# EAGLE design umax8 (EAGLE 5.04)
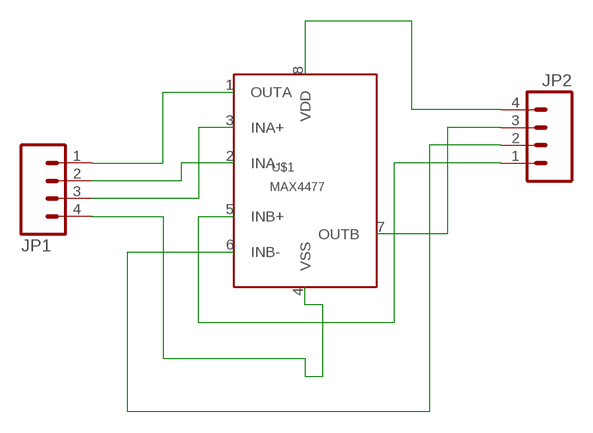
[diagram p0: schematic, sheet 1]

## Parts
JP1  M04PTH  [1X04]
JP2  M04PTH  [1X04]
U$1  MAX4477  [UMAX8]

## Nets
N$1: JP1.1 U$1.1(OUTA)
N$2: JP1.2 U$1.2(INA-)
N$3: JP1.3 U$1.3(INA+)
N$4: JP1.4 U$1.4(VSS)
N$5: JP2.1 U$1.5(INB+)
N$6: JP2.2 U$1.6(INB-)
N$7: JP2.3 U$1.7(OUTB)
N$8: JP2.4 U$1.8(VDD)

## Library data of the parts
JP1 JP2 = SparkFun:M04: Header 4 Standard 4-pin 0.1" header. Use with straight break away headers (SKU : PRT-00116), right angle break away headers (PRT-00553), swiss pins (PRT-00743), machine pins (PRT-00117), and female headers (PRT-00115). Molex polarized connector foot print use with SKU : PRT-08231 with associated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
U$1 = trl:MAX4477

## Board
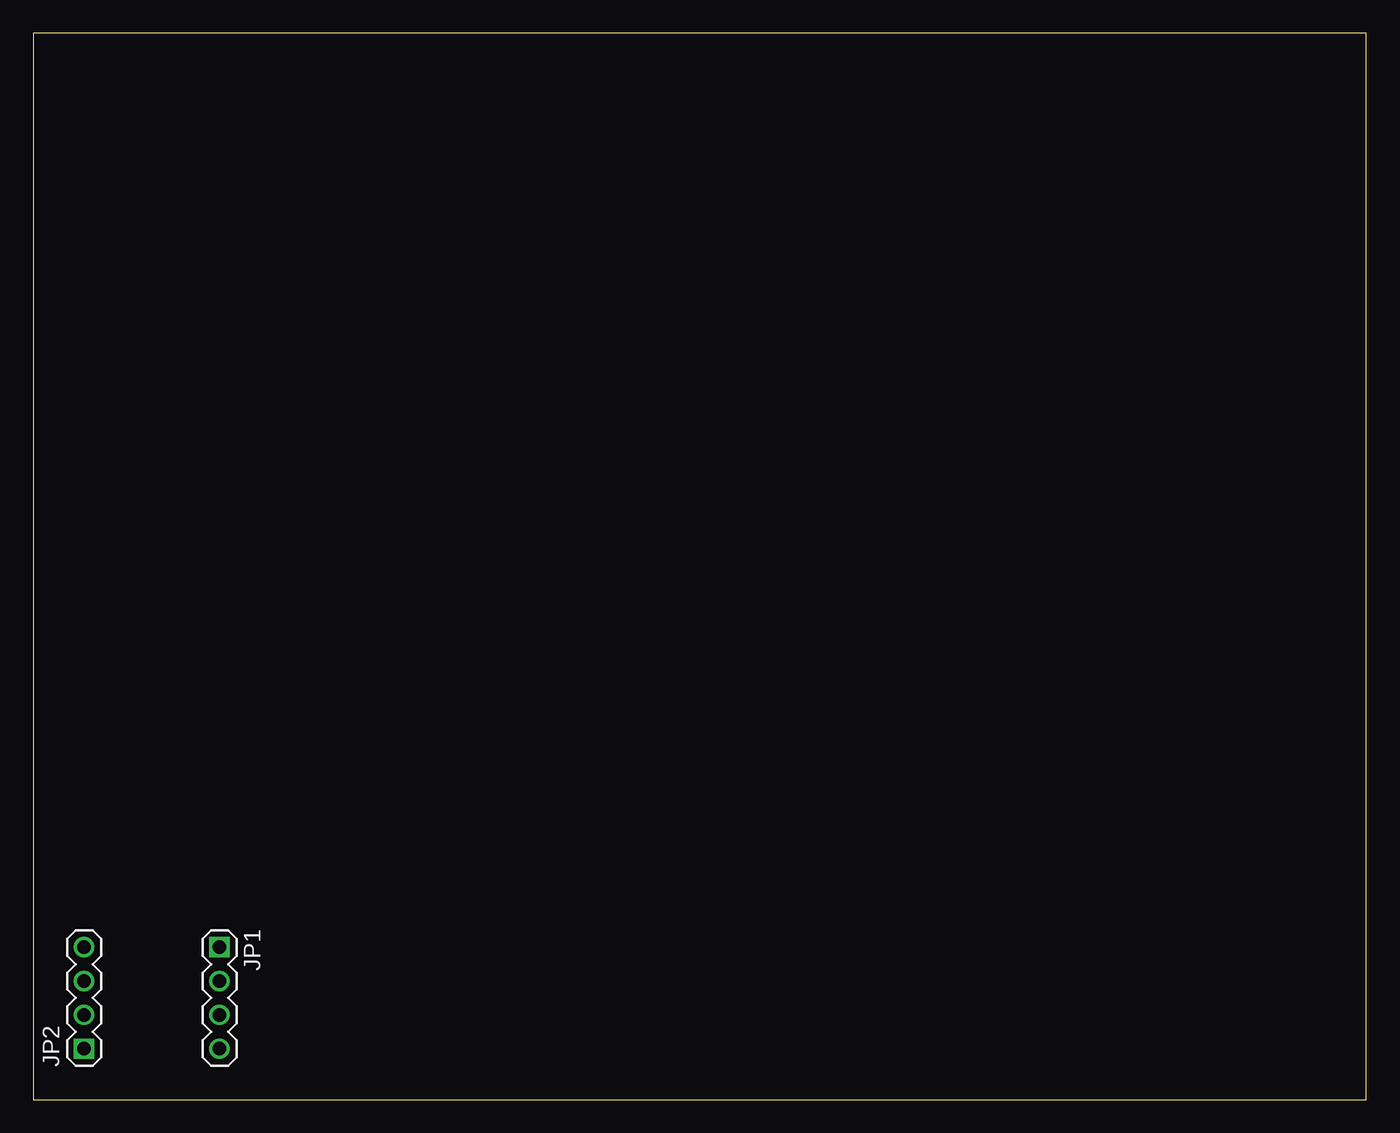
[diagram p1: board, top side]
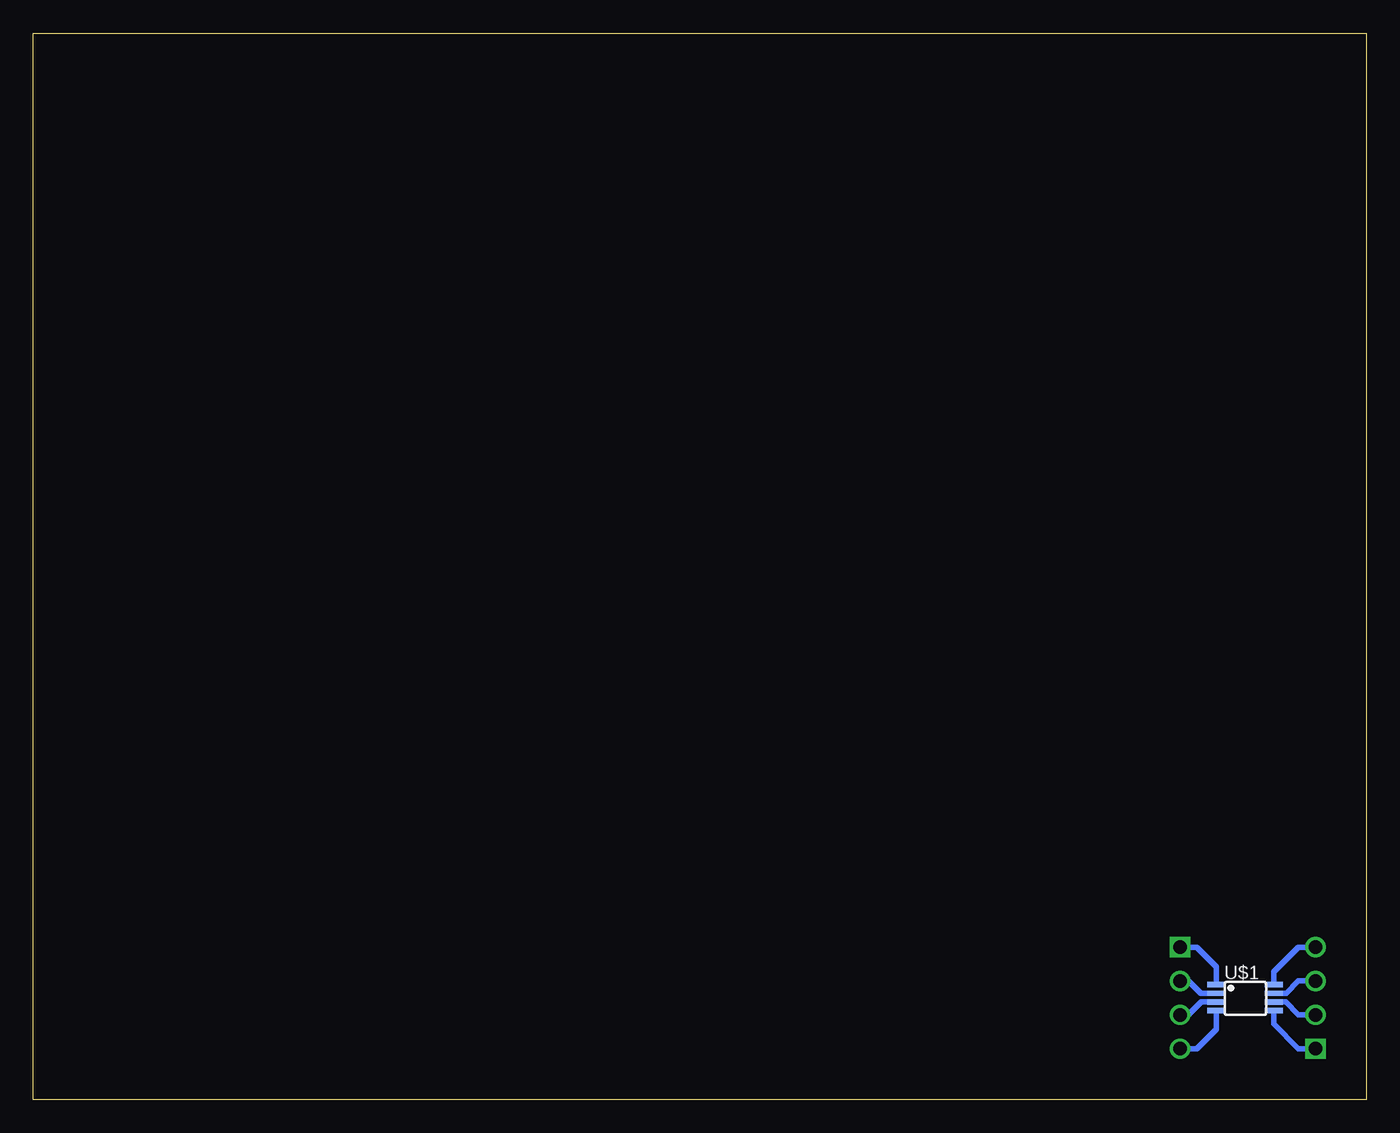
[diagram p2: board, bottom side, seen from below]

Size 100 x 80 mm. Coordinates in mm from the lower left corner, seen from the top.
Outline: 0,0 100,0 100,80 0,80 0,0
Copper layers (1*16): Top 0.035mm / dielectric 1.5mm / Bottom 0.035mm
Design rules "default": minimum track width 10mil, minimum drill 24mil, track to track 8mil, track to pad 8mil, pad to pad 8mil, via to via 8mil, smd to smd 8mil, copper to edge 40mil, drill to drill 8mil, minimum pad ring 10mil, minimum via ring 8mil, stop-mask expansion 4mil, vias tented up to drill 0mil, thermal gap 10mil

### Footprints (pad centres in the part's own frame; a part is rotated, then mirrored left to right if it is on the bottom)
1X04 = drill 1.016 square: 1 0,0 | drill 1.016 round: 2 2.54,0; 3 5.08,0; 4 7.62,0
UMAX8 = smd 1.35 x 0.4: 1 -2.35,1; 2 -2.35,0.35; 3 -2.35,-0.3; 4 -2.35,-0.95; 5 1.95,-0.95; 6 1.95,-0.3; 7 1.95,0.35; 8 1.95,1

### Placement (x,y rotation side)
JP1  13.97,11.43 270 top
JP2  3.81,3.81 90 top
U$1  8.89,7.62 0 bottom

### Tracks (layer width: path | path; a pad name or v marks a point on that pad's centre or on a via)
N$1
  Bottom 0.406: U$1.1 11.24,9.97 12.7,11.43 JP1.1
N$2
  Bottom 0.406: U$1.2 11.78,7.97 12.41,7.97 12.7,8.26 13.34,8.89 JP1.2
N$3
  Bottom 0.406: U$1.3 11.73,7.32 12.37,7.32 13.34,6.35 JP1.3
N$4
  Bottom 0.406: U$1.4 11.24,5.27 12.7,3.81 JP1.4
N$5
  Bottom 0.406: U$1.5 6.94,5.67 5.08,3.81 JP2.1
N$6
  Bottom 0.406: U$1.6 6.05,7.32 5.08,6.35 JP2.2
N$7
  Bottom 0.406: U$1.7 6,7.97 5.08,8.89 JP2.3
N$8
  Bottom 0.406: U$1.8 6.94,9.57 5.08,11.43 JP2.4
